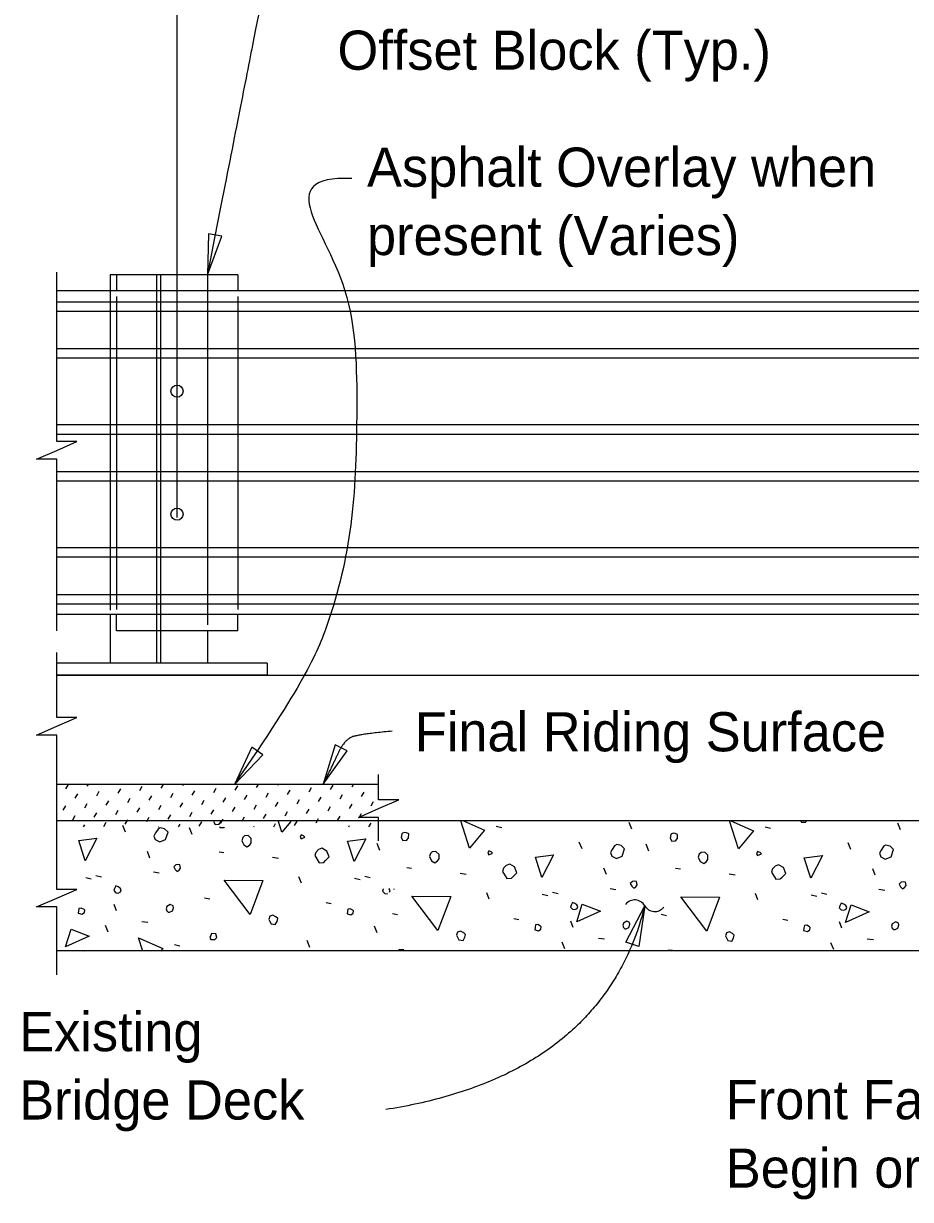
# Model space of a CAD drawing. Extents: x 21526.6 to 21595.9, y 56114.9 to 56157.2.
# Drawn here: x 21546.22 to 21550.79, y 56132.51 to 56138.57 of the extents above; entities that cross this region are included whole.
import ezdxf

# ---------------------------------------------------------------- set-up
doc = ezdxf.new("R2010")
doc.units = 0
for name, color, linetype in [('AdhocPoint_dp', 7, 'Continuous'), ('Border', 7, 'Continuous'), ('Patterning', 7, 'Continuous'), ('PlotBorder_dp', 7, 'Continuous'), ('SheetBorder_dp', 7, 'Continuous'), ('TextMisc', 7, 'Continuous')]:
    doc.layers.add(name, color=color, linetype=linetype)

msp = doc.modelspace()

# ---------------------------------------------------------------- linework, layer by layer
at = {"layer": 'AdhocPoint_dp'}
for p, q in [((21546.3955, 56135.21), (21554.1792, 56135.21)), ((21548.0534, 56134.6483), (21546.3955, 56134.6483)), ((21554.1792, 56134.46), (21546.3955, 56134.46)), ((21546.3955, 56133.7933), (21554.1792, 56133.7933))]:
    msp.add_line(p, q, dxfattribs=at)
at = {"layer": 'Patterning'}
for p, q in [((21547.0151, 56136.0224), (21547.0151, 56142.7213)), ((21547.3276, 56137.2726), (21546.7026, 56137.2726)), ((21546.7026, 56137.2726), (21546.7026, 56137.1892)), ((21547.3276, 56137.2726), (21547.3276, 56137.1892)), ((21546.7026, 56137.1607), (21546.7026, 56135.5488)), ((21547.3276, 56137.1607), (21547.3276, 56135.5488)), ((21546.7026, 56135.4392), (21546.7026, 56135.5226)), ((21547.3276, 56135.4392), (21547.3276, 56135.5226)), ((21547.3276, 56135.4392), (21546.7026, 56135.4392)), ((21546.4424, 56134.6258), (21546.4553, 56134.6482)), ((21546.553, 56134.6388), (21546.5585, 56134.6483)), ((21546.8231, 56134.6159), (21546.8361, 56134.6383)), ((21546.9337, 56134.6289), (21546.945, 56134.6483)), ((21547.0444, 56134.6418), (21547.0481, 56134.6483)), ((21547.3145, 56134.6189), (21547.3274, 56134.6413)), ((21547.4251, 56134.6319), (21547.4346, 56134.6483)), ((21547.5357, 56134.6448), (21547.5378, 56134.6483)), ((21547.8058, 56134.6219), (21547.8188, 56134.6443)), ((21547.9165, 56134.6349), (21547.9242, 56134.6483)), ((21548.0271, 56134.6479), (21548.0274, 56134.6483)), ((21546.4912, 56134.577), (21546.5042, 56134.5994)), ((21546.6018, 56134.59), (21546.6148, 56134.6124)), ((21546.7125, 56134.6029), (21546.7254, 56134.6253)), ((21546.7613, 56134.5541), (21546.7743, 56134.5765)), ((21546.8719, 56134.5671), (21546.8849, 56134.5894)), ((21546.9826, 56134.58), (21546.9955, 56134.6024)), ((21547.0932, 56134.593), (21547.1062, 56134.6154)), ((21547.2038, 56134.6059), (21547.2168, 56134.6283)), ((21547.2527, 56134.5571), (21547.2656, 56134.5795)), ((21547.3633, 56134.5701), (21547.3763, 56134.5925)), ((21547.4739, 56134.583), (21547.4869, 56134.6054)), ((21547.5846, 56134.596), (21547.5975, 56134.6184)), ((21547.6952, 56134.609), (21547.7082, 56134.6314)), ((21547.744, 56134.5601), (21547.757, 56134.5825)), ((21547.8547, 56134.5731), (21547.8676, 56134.5955)), ((21547.9653, 56134.5861), (21547.9783, 56134.6084)), ((21546.4294, 56134.5152), (21546.4424, 56134.5376)), ((21546.54, 56134.5282), (21546.553, 56134.5506)), ((21546.6507, 56134.5411), (21546.6636, 56134.5635)), ((21546.8101, 56134.5053), (21546.8231, 56134.5276)), ((21546.9208, 56134.5182), (21546.9337, 56134.5406)), ((21547.0314, 56134.5312), (21547.0444, 56134.5536)), ((21547.142, 56134.5441), (21547.155, 56134.5665)), ((21547.1909, 56134.4953), (21547.2038, 56134.5177)), ((21547.3015, 56134.5083), (21547.3145, 56134.5307)), ((21547.4121, 56134.5212), (21547.4251, 56134.5436)), ((21547.5228, 56134.5342), (21547.5357, 56134.5566)), ((21547.6334, 56134.5472), (21547.6464, 56134.5696)), ((21547.6822, 56134.4983), (21547.6952, 56134.5207)), ((21547.7929, 56134.5113), (21547.8058, 56134.5337)), ((21547.9035, 56134.5243), (21547.9165, 56134.5467)), ((21548.0141, 56134.5372), (21548.0271, 56134.5596)), ((21546.4782, 56134.4664), (21546.4912, 56134.4888)), ((21546.5889, 56134.4793), (21546.6018, 56134.5017)), ((21546.6995, 56134.4923), (21546.7125, 56134.5147)), ((21546.7483, 56134.4435), (21546.7613, 56134.4658)), ((21546.859, 56134.4564), (21546.8719, 56134.4788)), ((21546.9696, 56134.4694), (21546.9826, 56134.4918)), ((21547.0802, 56134.4823), (21547.0932, 56134.5047)), ((21547.1291, 56134.4335), (21547.142, 56134.4559)), ((21547.2397, 56134.4465), (21547.2527, 56134.4689)), ((21547.3503, 56134.4594), (21547.3633, 56134.4818)), ((21547.461, 56134.4724), (21547.4739, 56134.4948)), ((21547.5716, 56134.4854), (21547.5846, 56134.5078)), ((21547.6204, 56134.4365), (21547.6334, 56134.4589)), ((21547.7311, 56134.4495), (21547.744, 56134.4719)), ((21547.8417, 56134.4625), (21547.8547, 56134.4849)), ((21547.9523, 56134.4754), (21547.9653, 56134.4978)), ((21548.063, 56134.4884), (21548.0631, 56134.4886)), ((21546.5339, 56134.4293), (21546.54, 56134.4399)), ((21546.6377, 56134.4305), (21546.6507, 56134.4529)), ((21546.7494, 56134.4017), (21546.7352, 56134.4371)), ((21546.9204, 56134.4293), (21546.9208, 56134.43)), ((21547.0235, 56134.4293), (21547.0314, 56134.4429)), ((21547.0935, 56134.3899), (21547.0793, 56134.4253)), ((21547.41, 56134.4293), (21547.4121, 56134.433)), ((21547.5132, 56134.4293), (21547.5228, 56134.446)), ((21547.8996, 56134.4293), (21547.9035, 56134.436)), ((21548.0028, 56134.4293), (21548.0141, 56134.449)), ((21548.659, 56134.4328), (21548.6873, 56134.4258)), ((21549.3573, 56134.4169), (21549.3431, 56134.4523)), ((21550.0437, 56134.4293), (21550.072, 56134.4222)), ((21550.742, 56134.4134), (21550.7278, 56134.4487)), ((21548.0604, 56134.3079), (21548.0462, 56134.3433)), ((21549.101, 56134.3162), (21549.0868, 56134.3515)), ((21549.4451, 56134.3044), (21549.4309, 56134.3398)), ((21550.4856, 56134.3126), (21550.4715, 56134.348)), ((21546.8749, 56134.2691), (21546.8625, 56134.3027)), ((21547.2313, 56134.3016), (21547.2561, 56134.298)), ((21547.5071, 56134.2733), (21547.5372, 56134.268)), ((21548.1983, 56134.2196), (21548.223, 56134.216)), ((21549.2265, 56134.1836), (21549.2141, 56134.2172)), ((21549.5829, 56134.216), (21549.6077, 56134.2125)), ((21550.6112, 56134.18), (21550.5988, 56134.2136)), ((21546.5449, 56134.169), (21546.5732, 56134.1619)), ((21546.5973, 56134.179), (21546.6256, 56134.1719)), ((21546.8937, 56134.1973), (21546.9238, 56134.192)), ((21547.6556, 56134.1389), (21547.6432, 56134.1725)), ((21547.9296, 56134.1654), (21547.9579, 56134.1584)), ((21547.982, 56134.1754), (21548.0103, 56134.1684)), ((21548.474, 56134.1913), (21548.5041, 56134.186)), ((21549.8587, 56134.1877), (21549.8888, 56134.1824)), ((21548.9489, 56134.0934), (21548.9772, 56134.0864)), ((21549.2453, 56134.1117), (21549.2753, 56134.1064)), ((21550.63, 56134.1082), (21550.66, 56134.1029)), ((21547.1571, 56134.0647), (21547.1836, 56134.0594)), ((21547.7829, 56134.0399), (21547.8094, 56134.0346)), ((21548.6225, 56134.0569), (21548.6102, 56134.0905)), ((21548.8965, 56134.0834), (21548.9248, 56134.0764)), ((21550.0072, 56134.0534), (21549.9948, 56134.087)), ((21550.2812, 56134.0799), (21550.3095, 56134.0728)), ((21550.3336, 56134.0899), (21550.3619, 56134.0828)), ((21546.7034, 56133.9964), (21546.691, 56134.0299)), ((21548.124, 56133.9827), (21548.1505, 56133.9774)), ((21549.5087, 56133.9791), (21549.5352, 56133.9738)), ((21546.661, 56133.8868), (21546.6468, 56133.9221)), ((21546.8336, 56133.9427), (21546.8654, 56133.9392)), ((21548.0457, 56133.8832), (21548.0315, 56133.9186)), ((21548.7498, 56133.9579), (21548.7763, 56133.9526)), ((21549.055, 56133.9108), (21549.0426, 56133.9444)), ((21550.1345, 56133.9544), (21550.161, 56133.9491)), ((21550.4397, 56133.9073), (21550.4273, 56133.9409)), ((21549.1852, 56133.8572), (21549.217, 56133.8536)), ((21550.5699, 56133.8536), (21550.6017, 56133.8501)), ((21547.0015, 56133.8243), (21547.0298, 56133.8172)), ((21547.6998, 56133.8084), (21547.6857, 56133.8437)), ((21549.0126, 56133.8012), (21548.9984, 56133.8366)), ((21550.3973, 56133.7977), (21550.3831, 56133.833))]:
    msp.add_line(p, q, dxfattribs=at)
for points in [[(21547.2033, 56134.4566), (21547.2119, 56134.4412), (21547.2313, 56134.443), (21547.2402, 56134.4554), (21547.2403, 56134.4566)], [(21547.5548, 56134.4023), (21547.5372, 56134.4566)], [(21547.6008, 56134.4566), (21547.5548, 56134.4023)], [(21548.5218, 56134.3203), (21548.4763, 56134.46)], [(21548.4902, 56134.46), (21548.5995, 56134.4122), (21548.5218, 56134.3203)], [(21549.9064, 56134.3168), (21549.8599, 56134.46)], [(21549.8668, 56134.46), (21549.9842, 56134.4087), (21549.9064, 56134.3168)], [(21550.2285, 56134.46), (21550.2311, 56134.454), (21550.2275, 56134.4576)], [(21550.2311, 56134.454), (21550.2523, 56134.454), (21550.2582, 56134.46)], [(21546.9032, 56134.3646), (21546.9261, 56134.3522), (21546.9562, 56134.3646), (21546.9686, 56134.4017), (21546.9509, 56134.4194), (21546.9279, 56134.4247), (21546.9173, 56134.4176), (21546.9049, 56134.3982), (21546.8961, 56134.3823), (21546.9032, 56134.3646)], [(21547.2354, 56134.4293), (21547.2364, 56134.4269), (21547.234, 56134.4293)], [(21547.2364, 56134.4269), (21547.2576, 56134.4269), (21547.2601, 56134.4293)], [(21548.17, 56134.3751), (21548.1788, 56134.3592), (21548.1983, 56134.361), (21548.2071, 56134.3734), (21548.2089, 56134.3928), (21548.1965, 56134.3981), (21548.1877, 56134.3999), (21548.177, 56134.3963), (21548.1735, 56134.3928), (21548.17, 56134.3751)], [(21549.5547, 56134.3716), (21549.5635, 56134.3557), (21549.5829, 56134.3574), (21549.5918, 56134.3698), (21549.5935, 56134.3893), (21549.5812, 56134.3946), (21549.5723, 56134.3963), (21549.5617, 56134.3928), (21549.5582, 56134.3893), (21549.5547, 56134.3716)], [(21546.5425, 56134.255), (21546.509, 56134.3593), (21546.6026, 56134.3716), (21546.5425, 56134.255)], [(21547.348, 56134.3581), (21547.3586, 56134.3369), (21547.3763, 56134.3263), (21547.3904, 56134.3369), (21547.3975, 56134.3475), (21547.3975, 56134.3687), (21547.3816, 56134.3846), (21547.3622, 56134.3829), (21547.3533, 56134.374), (21547.348, 56134.3581)], [(21547.6538, 56134.367), (21547.6733, 56134.3758), (21547.6662, 56134.3829), (21547.6538, 56134.3882), (21547.6485, 56134.3758), (21547.6538, 56134.367)], [(21547.9272, 56134.2514), (21547.8936, 56134.3557), (21547.9873, 56134.3681), (21547.9272, 56134.2514)], [(21549.2548, 56134.279), (21549.2777, 56134.2667), (21549.3078, 56134.279), (21549.3202, 56134.3162), (21549.3025, 56134.3338), (21549.2795, 56134.3391), (21549.2689, 56134.3321), (21549.2565, 56134.3126), (21549.2477, 56134.2967), (21549.2548, 56134.279)], [(21550.6394, 56134.2755), (21550.6624, 56134.2631), (21550.6925, 56134.2755), (21550.7048, 56134.3126), (21550.6872, 56134.3303), (21550.6642, 56134.3356), (21550.6536, 56134.3285), (21550.6412, 56134.3091), (21550.6324, 56134.2932), (21550.6394, 56134.2755)], [(21547.7245, 56134.2821), (21547.7475, 56134.245), (21547.7705, 56134.2468), (21547.7793, 56134.2556), (21547.7988, 56134.275), (21547.7864, 56134.3051), (21547.7617, 56134.3192), (21547.744, 56134.3122), (21547.7299, 56134.298), (21547.7245, 56134.2821)], [(21548.3149, 56134.2761), (21548.3255, 56134.2549), (21548.3432, 56134.2443), (21548.3574, 56134.2549), (21548.3644, 56134.2655), (21548.3644, 56134.2867), (21548.3485, 56134.3026), (21548.3291, 56134.3009), (21548.3202, 56134.292), (21548.3149, 56134.2761)], [(21548.6208, 56134.285), (21548.6402, 56134.2938), (21548.6331, 56134.3009), (21548.6208, 56134.3062), (21548.6155, 56134.2938), (21548.6208, 56134.285)], [(21548.8941, 56134.1694), (21548.8605, 56134.2737), (21548.9542, 56134.2861), (21548.8941, 56134.1694)], [(21549.6996, 56134.2726), (21549.7102, 56134.2514), (21549.7279, 56134.2408), (21549.742, 56134.2514), (21549.7491, 56134.262), (21549.7491, 56134.2832), (21549.7332, 56134.2991), (21549.7138, 56134.2973), (21549.7049, 56134.2885), (21549.6996, 56134.2726)], [(21550.0054, 56134.2814), (21550.0249, 56134.2903), (21550.0178, 56134.2973), (21550.0054, 56134.3026), (21550.0001, 56134.2903), (21550.0054, 56134.2814)], [(21550.2788, 56134.1659), (21550.2452, 56134.2702), (21550.3389, 56134.2826), (21550.2788, 56134.1659)], [(21547.0051, 56134.2096), (21547.0157, 56134.199), (21547.0263, 56134.2061), (21547.0334, 56134.2167), (21547.0298, 56134.2344), (21547.021, 56134.2362), (21547.0086, 56134.2344), (21546.998, 56134.2238), (21547.0051, 56134.2096)], [(21548.6915, 56134.2001), (21548.7145, 56134.163), (21548.7374, 56134.1648), (21548.7463, 56134.1736), (21548.7657, 56134.193), (21548.7533, 56134.2231), (21548.7286, 56134.2372), (21548.7109, 56134.2302), (21548.6968, 56134.216), (21548.6915, 56134.2001)], [(21550.0761, 56134.1966), (21550.0991, 56134.1595), (21550.1221, 56134.1612), (21550.1309, 56134.1701), (21550.1504, 56134.1895), (21550.138, 56134.2196), (21550.1133, 56134.2337), (21550.0956, 56134.2266), (21550.0815, 56134.2125), (21550.0761, 56134.1966)], [(21547.3922, 56133.9781), (21547.2579, 56134.1548), (21547.4576, 56134.1531), (21547.3922, 56133.9781)], [(21546.6999, 56134.0906), (21546.7122, 56134.0888), (21546.7246, 56134.0941), (21546.7282, 56134.1047), (21546.7229, 56134.1136), (21546.7122, 56134.1206), (21546.6999, 56134.1259), (21546.6928, 56134.1118), (21546.6893, 56134.1012), (21546.6999, 56134.0906)], [(21548.0789, 56134.1111), (21548.0775, 56134.1082), (21548.0739, 56134.0976), (21548.0845, 56134.087)], [(21548.1101, 56134.0931), (21548.1128, 56134.1012), (21548.1075, 56134.11), (21548.1059, 56134.1111)], [(21548.133, 56134.1072), (21548.1342, 56134.1111)], [(21549.3567, 56134.1241), (21549.3673, 56134.1135), (21549.3779, 56134.1206), (21549.3849, 56134.1312), (21549.3814, 56134.1488), (21549.3726, 56134.1506), (21549.3602, 56134.1488), (21549.3496, 56134.1382), (21549.3567, 56134.1241)], [(21550.7413, 56134.1206), (21550.7519, 56134.11), (21550.7626, 56134.117), (21550.7696, 56134.1276), (21550.7661, 56134.1453), (21550.7573, 56134.1471), (21550.7449, 56134.1453), (21550.7343, 56134.1347), (21550.7413, 56134.1206)], [(21548.0845, 56134.087), (21548.0969, 56134.0853), (21548.0988, 56134.0861)], [(21548.3591, 56133.8961), (21548.2248, 56134.0728), (21548.4245, 56134.0711), (21548.3591, 56133.8961)], [(21549.0515, 56134.005), (21549.0638, 56134.0033), (21549.0762, 56134.0086), (21549.0798, 56134.0192), (21549.0744, 56134.028), (21549.0638, 56134.0351), (21549.0515, 56134.0404), (21549.0444, 56134.0262), (21549.0409, 56134.0156), (21549.0515, 56134.005)], [(21549.0738, 56133.9403), (21549.1021, 56134.0322), (21549.1958, 56133.9951), (21549.0738, 56133.9403)], [(21549.7438, 56133.8925), (21549.6095, 56134.0693), (21549.8092, 56134.0675), (21549.7438, 56133.8925)], [(21550.4361, 56134.0015), (21550.4485, 56133.9997), (21550.4609, 56134.005), (21550.4644, 56134.0156), (21550.4591, 56134.0245), (21550.4485, 56134.0316), (21550.4361, 56134.0369), (21550.4291, 56134.0227), (21550.4255, 56134.0121), (21550.4361, 56134.0015)], [(21546.506, 56133.9851), (21546.5255, 56133.9798), (21546.5379, 56133.9887), (21546.5396, 56134.001), (21546.5361, 56134.0046), (21546.522, 56134.0116), (21546.5096, 56134.0099), (21546.5078, 56133.9975), (21546.506, 56133.9851)], [(21546.9697, 56133.9904), (21546.9768, 56133.9904), (21546.9909, 56133.9975), (21546.9962, 56134.0134), (21546.9945, 56134.0223), (21546.9803, 56134.0293), (21546.9626, 56134.0187), (21546.9591, 56134.0081), (21546.9626, 56133.9975), (21546.9697, 56133.9904)], [(21547.4912, 56133.9462), (21547.5, 56133.9303), (21547.5213, 56133.9268), (21547.5301, 56133.9427), (21547.5336, 56133.9568), (21547.5248, 56133.9657), (21547.5089, 56133.9745), (21547.493, 56133.9692), (21547.4877, 56133.9533), (21547.4912, 56133.9462)], [(21547.8907, 56133.9816), (21547.9102, 56133.9763), (21547.9225, 56133.9851), (21547.9243, 56133.9975), (21547.9208, 56134.001), (21547.9066, 56134.0081), (21547.8943, 56134.0063), (21547.8925, 56133.994), (21547.8907, 56133.9816)], [(21550.4585, 56133.9367), (21550.4868, 56134.0286), (21550.5805, 56133.9915), (21550.4585, 56133.9367)], [(21548.8576, 56133.8996), (21548.8771, 56133.8943), (21548.8895, 56133.9031), (21548.8912, 56133.9155), (21548.8877, 56133.919), (21548.8735, 56133.9261), (21548.8612, 56133.9243), (21548.8594, 56133.912), (21548.8576, 56133.8996)], [(21549.3213, 56133.9049), (21549.3284, 56133.9049), (21549.3425, 56133.912), (21549.3478, 56133.9279), (21549.3461, 56133.9367), (21549.3319, 56133.9438), (21549.3142, 56133.9332), (21549.3107, 56133.9226), (21549.3142, 56133.912), (21549.3213, 56133.9049)], [(21550.2423, 56133.8961), (21550.2618, 56133.8908), (21550.2741, 56133.8996), (21550.2759, 56133.912), (21550.2724, 56133.9155), (21550.2582, 56133.9226), (21550.2459, 56133.9208), (21550.2441, 56133.9084), (21550.2423, 56133.8961)], [(21550.706, 56133.9014), (21550.7131, 56133.9014), (21550.7272, 56133.9084), (21550.7325, 56133.9243), (21550.7307, 56133.9332), (21550.7166, 56133.9403), (21550.6989, 56133.9296), (21550.6954, 56133.919), (21550.6989, 56133.9084), (21550.706, 56133.9014)], [(21546.4412, 56133.8116), (21546.4695, 56133.9035), (21546.5632, 56133.8664), (21546.4412, 56133.8116)], [(21546.8388, 56133.79), (21546.8165, 56133.8585), (21546.9421, 56133.8037), (21546.9305, 56133.79)], [(21547.1889, 56133.849), (21547.2101, 56133.849), (21547.2207, 56133.8596), (21547.2154, 56133.8791), (21547.1925, 56133.8808), (21547.1889, 56133.8702), (21547.1836, 56133.8614), (21547.1889, 56133.849), (21547.1854, 56133.8525)], [(21548.4581, 56133.8642), (21548.467, 56133.8483), (21548.4882, 56133.8448), (21548.497, 56133.8607), (21548.5006, 56133.8748), (21548.4917, 56133.8837), (21548.4758, 56133.8925), (21548.4599, 56133.8872), (21548.4546, 56133.8713), (21548.4581, 56133.8642)], [(21549.8428, 56133.8607), (21549.8516, 56133.8448), (21549.8729, 56133.8413), (21549.8817, 56133.8572), (21549.8852, 56133.8713), (21549.8764, 56133.8801), (21549.8605, 56133.889), (21549.8446, 56133.8837), (21549.8393, 56133.8678), (21549.8428, 56133.8607)], [(21546.5368, 56133.79), (21546.5302, 56133.7913), (21546.5262, 56133.79)], [(21548.1834, 56133.7933), (21548.1824, 56133.7971), (21548.1594, 56133.7988), (21548.1575, 56133.7933)], [(21549.5671, 56133.7933), (21549.567, 56133.7935), (21549.544, 56133.7953), (21549.5434, 56133.7933)]]:
    msp.add_lwpolyline(points, dxfattribs=at)
at = {"layer": 'PlotBorder_dp'}
for points in [[(21547.1713, 56137.2726), (21547.2461, 56137.4701), (21547.1768, 56137.4837)], [(21547.3105, 56134.6482), (21547.4577, 56134.7997), (21547.3996, 56134.8397)], [(21547.7672, 56134.6496), (21547.8919, 56134.8201), (21547.8288, 56134.8517)], [(21549.4247, 56134.0233), (21549.3942, 56133.8143), (21549.3271, 56133.836)]]:
    msp.add_lwpolyline(points, close=True, dxfattribs=at)
for points in [[(21546.3955, 56135.4395), (21546.3955, 56136.3228), (21546.2921, 56136.3228), (21546.3955, 56136.3678), (21546.4988, 56136.4128), (21546.3955, 56136.4128), (21546.3955, 56137.2857)], [(21546.3955, 56134.4321), (21546.3955, 56134.9022), (21546.2921, 56134.9022), (21546.3955, 56134.9472), (21546.4988, 56134.9922), (21546.3955, 56134.9922), (21546.3955, 56135.3267)], [(21548.0534, 56134.3575), (21548.0534, 56134.4784), (21547.9501, 56134.4784), (21548.0534, 56134.5234), (21548.1568, 56134.5684), (21548.0534, 56134.5684), (21548.0534, 56134.699)], [(21546.3955, 56133.667), (21546.3955, 56134.0177), (21546.2921, 56134.0177), (21546.3955, 56134.0627), (21546.4988, 56134.1077), (21546.3955, 56134.1077), (21546.3955, 56134.4321)]]:
    msp.add_lwpolyline(points, dxfattribs=at)
for centre, start, end in [((21549.3723, 56133.9936), 30.00813, 141.73535), ((21549.4755, 56134.0532), 210.00813, 321.73535)]:
    msp.add_arc(centre, 0.0596, start, end, dxfattribs=at)
for points, degree in [([(21550.3735, 56139.7107), (21550.642, 56139.7107), (21550.7763, 56139.5622), (21551.5367, 56138.4496), (21551.5303, 56137.6074), (21551.6724, 56137.1865)], 2), ([(21547.7365, 56139.0917), (21547.573, 56139.0917), (21547.5207, 56139.0394), (21547.4226, 56138.552), (21547.1713, 56137.2726)], 2), ([(21547.9147, 56137.7671), (21547.7027, 56137.7777), (21547.6407, 56137.6336), (21547.9384, 56137.195), (21547.9442, 56136.5212), (21547.927, 56135.9787), (21547.8072, 56135.4705), (21547.6617, 56135.1578), (21547.3105, 56134.6481)], 3), ([(21548.1235, 56134.922), (21547.9499, 56134.9066), (21547.8757, 56134.8752), (21547.8101, 56134.7353), (21547.7672, 56134.6496)], 2), ([(21549.4247, 56134.0233), (21549.2041, 56133.1495), (21548.0898, 56132.9735)], 2)]:
    msp.add_open_spline(points, degree=degree, dxfattribs=at)
at = {"layer": 'SheetBorder_dp'}
for p, q in [((21546.6713, 56137.2726), (21546.6713, 56135.5456)), ((21546.9109, 56135.2726), (21546.9109, 56137.2726)), ((21546.9317, 56135.2726), (21546.9317, 56137.2726)), ((21547.1713, 56137.2726), (21547.1713, 56135.4691))]:
    msp.add_line(p, q, dxfattribs=at)
at = {"layer": 'TextMisc'}
for p, q in [((21547.1713, 56137.2726), (21546.6713, 56137.2726)), ((21552.8484, 56137.1892), (21546.3955, 56137.1892)), ((21546.3955, 56137.1336), (21552.8484, 56137.1336)), ((21546.3955, 56137.0854), (21552.8484, 56137.0854)), ((21546.3955, 56136.8926), (21552.8484, 56136.8926)), ((21546.3955, 56136.8444), (21552.8484, 56136.8444)), ((21546.3955, 56136.5004), (21552.8484, 56136.5004)), ((21546.3955, 56136.4522), (21552.8484, 56136.4522)), ((21546.3955, 56136.2594), (21552.8484, 56136.2594)), ((21546.3955, 56136.2112), (21552.8484, 56136.2112)), ((21546.3955, 56135.8673), (21552.8484, 56135.8673)), ((21546.3955, 56135.8191), (21552.8484, 56135.8191)), ((21546.3955, 56135.6262), (21552.8484, 56135.6262)), ((21546.3955, 56135.578), (21552.8484, 56135.578)), ((21552.8484, 56135.5225), (21546.3955, 56135.5225)), ((21546.6713, 56135.5225), (21546.6713, 56135.2726)), ((21547.1713, 56135.4392), (21547.1713, 56135.2726)), ((21547.4788, 56135.2726), (21546.3955, 56135.2726)), ((21547.1713, 56135.2726), (21546.6713, 56135.2726)), ((21547.4788, 56135.2726), (21547.4788, 56135.2101)), ((21547.4788, 56135.2101), (21546.3955, 56135.2101))]:
    msp.add_line(p, q, dxfattribs=at)
for centre in [(21547.0151, 56136.6725), (21547.0151, 56136.0393)]:
    msp.add_circle(centre, 0.0312, dxfattribs=at)

# ---------------------------------------------------------------- texts
at = {"layer": 'Border'}
msp.add_text('Final Riding Surface', height=0.2016, dxfattribs=at).set_placement((21548.2396, 56134.8183))
at = {"layer": 'PlotBorder_dp'}
for s, p in [('Offset Block (Typ.)', (21547.8417, 56138.3277)), ('Asphalt Overlay when', (21547.9936, 56137.7254)), ('present (Varies)', (21547.9936, 56137.3734)), ('Existing ', (21546.2023, 56133.2744)), ('Bridge Deck', (21546.2023, 56132.9224)), ('Front Face of Backwall &', (21549.8416, 56132.9237)), ('Begin or End Bridge', (21549.8416, 56132.5717))]:
    msp.add_text(s, height=0.2016, dxfattribs=at).set_placement(p)

doc.saveas('drawing.dxf')
